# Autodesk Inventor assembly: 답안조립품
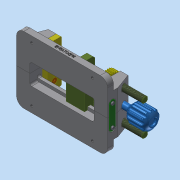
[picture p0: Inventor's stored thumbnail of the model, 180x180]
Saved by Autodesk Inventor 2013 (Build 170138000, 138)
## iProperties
Created: 2018-03
Part Number: 답안조립품
Document SubType Name: Assembly
Designer: dgall
Mass: 1034.81 g
Surface Area: 918.51 cm^2
Volume: 340.422 cm^3
Density: 3.0398 g/cm^3
Author: dgall
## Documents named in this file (10)
- C:\Users\dgall\Desktop\380307V1023\답안조립품.iam
- C:\Users\dgall\Desktop\380307V1023\바이스본체 A.ipt
- C:\Users\dgall\Desktop\380307V1023\바이스본체 B.ipt
- C:\Users\dgall\Desktop\380307V1023\핸들.ipt
- C:\Users\dgall\Desktop\380307V1023\고정 플레이트.ipt
- C:\Users\dgall\Desktop\380307V1023\슬라이딩 부품.ipt
- C:\Users\dgall\Desktop\380307V1023\스퍼기어.ipt
- C:\Users\dgall\Desktop\380307V1023\지지대.ipt
- C:\Users\dgall\Desktop\380307V1023\십자오목머리나사 M4.ipt
- C:\Users\dgall\Desktop\380307V1023\십자오목머리나사 M3.ipt
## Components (3 placed, 2 different names)
1. 핸들:1
2. 고정 플레이트:1
3. 고정 플레이트:2
